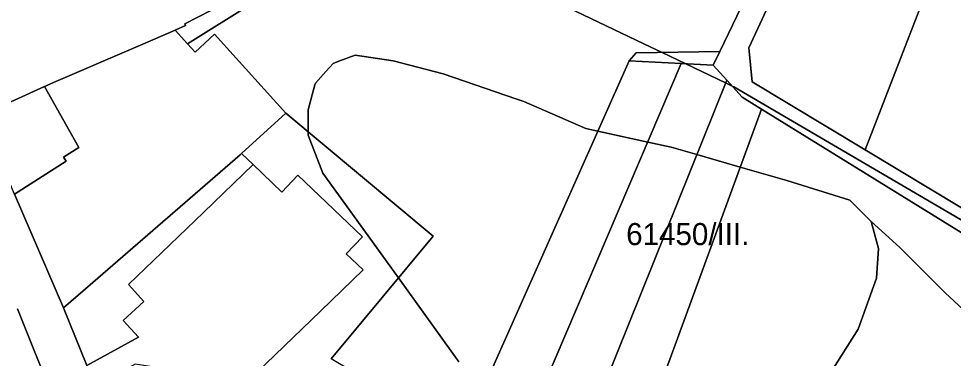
# Model space of a CAD drawing. Extents: x -522079 to -518833, y -1142400 to -1139961.
# Drawn here: x -520338.9 to -520127.5, y -1141019.5 to -1140942.7 of the extents above; entities that cross this region are included whole.
import ezdxf

# ---------------------------------------------------------------- set-up
doc = ezdxf.new("R2010")
doc.units = 0
for name, color, linetype in [('95560013', 7, 'Continuous'), ('95590013', 7, 'Continuous'), ('95610013', 7, 'Continuous'), ('95640013', 7, 'Continuous'), ('95660013', 7, 'Continuous')]:
    doc.layers.add(name, color=color, linetype=linetype)

msp = doc.modelspace()

# ---------------------------------------------------------------- linework, layer by layer
at = {"layer": '95560013'}
msp.add_lwpolyline([(-520205.51, -1141057.7), (-520170.88, -1140963.13), (-520079.53, -1141019.58), (-520129.38, -1141144.09), (-520158.56, -1141206.98), (-520178.85, -1141202.22), (-520209, -1141207.86), (-520194.38, -1141159.65), (-520235.62, -1141148.58), (-520200.4, -1141059.73)], close=True, dxfattribs=at)
at = {"layer": '95590013'}
for points in [[(-520278.46, -1140964.1), (-520294.61, -1140946.2), (-520299.04, -1140950.24), (-520300.74, -1140948.36), (-520257.36, -1140921.21), (-520246.32, -1140932.55), (-520237.12, -1140923.52), (-520250.18, -1140910.34), (-520199.46, -1140857.65), (-520181.95, -1140869.32), (-520182.55, -1140869.96), (-520164.55, -1140881.96), (-520151.68, -1140896.26), (-520156.19, -1140899.86), (-520180.26, -1140950.09), (-520199.25, -1140950.43), (-520200.79, -1140952.24), (-520238.67, -1141037.33), (-520268.23, -1141019.69), (-520245.17, -1140991.88)], [(-520235.95, -1141044.56), (-520241.17, -1141042.05), (-520238.67, -1141037.33), (-520200.79, -1140952.24), (-520189.01, -1140952.86), (-520229.4, -1141047.39), (-520230.46, -1141046.93)], [(-520181.77, -1140953.24), (-520178.74, -1140956.58), (-520217.35, -1141052.59), (-520219.97, -1141051.46), (-520227.89, -1141048.04), (-520229.4, -1141047.39), (-520189.01, -1140952.86)], [(-520217.35, -1141052.59), (-520178.74, -1140956.58), (-520175.23, -1140960.44), (-520170.88, -1140963.13), (-520205.51, -1141057.7)]]:
    msp.add_lwpolyline(points, close=True, dxfattribs=at)
msp.add_lwpolyline([(-520295.32, -1141032.65), (-520270.67, -1141008.89), (-520260.98, -1140999.54), (-520264.81, -1140995.88), (-520261.15, -1140992.05), (-520275.75, -1140978.09), (-520279.41, -1140981.92), (-520285.91, -1140975.7), (-520288.51, -1140973.21), (-520278.46, -1140964.1), (-520245.17, -1140991.88), (-520268.23, -1141019.69)], dxfattribs=at)
at = {"layer": '95610013'}
for points in [[(-520154.18, -1140907.23), (-520136.24, -1140924.81), (-520129.31, -1140925.55), (-520147.43, -1140972.36), (-520172.97, -1140956.99), (-520173.77, -1140949.3)], [(-520129.31, -1140925.55), (-520124.49, -1140925.8), (-520100.12, -1140914.78), (-520097.88, -1140916.76), (-520125.63, -1140985.48), (-520147.43, -1140972.36)]]:
    msp.add_lwpolyline(points, close=True, dxfattribs=at)
at = {"layer": '95640013'}
for points in [[(-520079.53, -1141019.58), (-520170.88, -1140963.13), (-520175.23, -1140960.44), (-520178.74, -1140956.58), (-520181.77, -1140953.24), (-520180.26, -1140950.09), (-520156.19, -1140899.86), (-520151.68, -1140896.26), (-520149.94, -1140892.73), (-520146.75, -1140896.12), (-520154.18, -1140907.23), (-520173.77, -1140949.3), (-520172.97, -1140956.99), (-520147.43, -1140972.36), (-520125.63, -1140985.48), (-520084.54, -1141010.19), (-520030.55, -1141043.1), (-520027.48, -1141044.21), (-519988.12, -1141058.45), (-519949.16, -1141072.54), (-519944.08, -1141074.41), (-519948.1, -1141084.44), (-519951.21, -1141077.01), (-520032.33, -1141047.7)], [(-520301.23, -1140944.23), (-520301.37, -1140943.86), (-520295.5, -1140940.8), (-520294.04, -1140940.04), (-520260.36, -1140918.14), (-520255, -1140914.65), (-520250.52, -1140910), (-520250.18, -1140910.34), (-520237.12, -1140923.52), (-520246.32, -1140932.55), (-520257.36, -1140921.21), (-520300.74, -1140948.36), (-520303.52, -1140945.28)], [(-520301.23, -1140944.23), (-520303.52, -1140945.28), (-520311.37, -1140948.65), (-520312.42, -1140949.1), (-520330.57, -1140956.9), (-520333.07, -1140958.03), (-520347.56, -1140964.58), (-520357.85, -1140939.9), (-520356.86, -1140939.57), (-520333.64, -1140931.91), (-520328.35, -1140930.16), (-520327.1, -1140929.75), (-520320.68, -1140927.43), (-520309.29, -1140923.33), (-520304.25, -1140936.55), (-520303.17, -1140939.4), (-520297.35, -1140935.94), (-520295.5, -1140940.8), (-520301.37, -1140943.86)], [(-520333.07, -1140958.03), (-520330.57, -1140956.9), (-520312.42, -1140949.1), (-520311.37, -1140948.65), (-520303.52, -1140945.28), (-520300.74, -1140948.36), (-520299.04, -1140950.24), (-520294.61, -1140946.2), (-520278.46, -1140964.1), (-520288.51, -1140973.21), (-520288.83, -1140973.5), (-520322.15, -1141002.36), (-520328.8, -1141008.12), (-520339.88, -1140982.4), (-520336.31, -1140980.12), (-520328.21, -1140974.96), (-520328.8, -1140974.04), (-520325.3, -1140971.81)], [(-520181.77, -1140953.24), (-520189.01, -1140952.86), (-520200.79, -1140952.24), (-520199.25, -1140950.43), (-520180.26, -1140950.09)], [(-520333.07, -1140958.03), (-520325.3, -1140971.81), (-520328.8, -1140974.04), (-520328.21, -1140974.96), (-520336.31, -1140980.12), (-520339.88, -1140982.4), (-520347.56, -1140964.58)], [(-520310.61, -1141006.67), (-520315.31, -1141011.02), (-520311.83, -1141014.78), (-520323.52, -1141021.14), (-520328.8, -1141008.12), (-520322.15, -1141002.36), (-520288.83, -1140973.5), (-520288.51, -1140973.21), (-520285.91, -1140975.7), (-520297.15, -1140986.51), (-520314.09, -1141002.81)], [(-520261.15, -1140992.05), (-520264.81, -1140995.88), (-520260.98, -1140999.54), (-520270.67, -1141008.89), (-520295.32, -1141032.65), (-520299.78, -1141027.82), (-520301.02, -1141029.07), (-520307.7, -1141021.63), (-520312.58, -1141020.86), (-520321.6, -1141025.87), (-520323.52, -1141021.14), (-520311.83, -1141014.78), (-520315.31, -1141011.02), (-520310.61, -1141006.67), (-520314.09, -1141002.81), (-520297.15, -1140986.51), (-520285.91, -1140975.7), (-520279.41, -1140981.92), (-520275.75, -1140978.09)]]:
    msp.add_lwpolyline(points, close=True, dxfattribs=at)
for points in [[(-520339.88, -1140982.4), (-520328.8, -1141008.12), (-520323.52, -1141021.14)], [(-520339.2, -1141008.34), (-520330.66, -1141029.65), (-520324.76, -1141047.17), (-520321.07, -1141060.89), (-520319.27, -1141070.53), (-520318.44, -1141077.73), (-520317.76, -1141090.48), (-520318.04, -1141094.37), (-520318.78, -1141100.08), (-520325.12, -1141113.35), (-520332.74, -1141125.19), (-520337.15, -1141133.73), (-520339.09, -1141141.84)], [(-520339.09, -1141141.84), (-520337.15, -1141133.73), (-520332.74, -1141125.19), (-520325.12, -1141113.35), (-520318.78, -1141100.08), (-520318.04, -1141094.37), (-520317.76, -1141090.48), (-520318.44, -1141077.73), (-520319.27, -1141070.53), (-520321.07, -1141060.89), (-520324.76, -1141047.17), (-520330.66, -1141029.65), (-520339.2, -1141008.34)]]:
    msp.add_lwpolyline(points, dxfattribs=at)
at = {"layer": '95660013'}
for points in [[(-520000, -1141056.45), (-520011.71, -1141051.75), (-520029.88, -1141044.45), (-520090.04, -1141009.08), (-520177.16, -1140958.1), (-520177.51, -1140957.94), (-520179, -1140957.22), (-520187.97, -1140952.91), (-520193.37, -1140950.32), (-520197.48, -1140948.35), (-520236.79, -1140929.49), (-520241.05, -1140927.38), (-520260.08, -1140917.96), (-520260.95, -1140917.52), (-520263.93, -1140916.05), (-520267.12, -1140914.47), (-520274.28, -1140910.93), (-520277.76, -1140909.2), (-520287.26, -1140905.6), (-520291.47, -1140904.01), (-520313.41, -1140895.68), (-520320.28, -1140893.08), (-520338.07, -1140887.2), (-520355.25, -1140881.53)], [(-520355.25, -1140881.53), (-520338.07, -1140887.2), (-520320.28, -1140893.08), (-520313.41, -1140895.68), (-520291.47, -1140904.01), (-520287.26, -1140905.6), (-520277.76, -1140909.2), (-520274.28, -1140910.93), (-520267.12, -1140914.47), (-520263.93, -1140916.05), (-520260.95, -1140917.52), (-520260.08, -1140917.96), (-520241.05, -1140927.38), (-520236.79, -1140929.49), (-520197.48, -1140948.35), (-520193.37, -1140950.32), (-520187.97, -1140952.91), (-520179, -1140957.22), (-520177.51, -1140957.94), (-520177.16, -1140958.1), (-520090.04, -1141009.08), (-520029.88, -1141044.45), (-520011.71, -1141051.75), (-520000, -1141056.45)], [(-520097.47, -1141034.19), (-520129.32, -1141004.76), (-520132.12, -1141001.95), (-520139.58, -1140994.46), (-520146.08, -1140988.57), (-520150.9, -1140983.74), (-520165.15, -1140979.32), (-520175.69, -1140976.27), (-520185.52, -1140973.44), (-520191.34, -1140971.76), (-520196.59, -1140970.61), (-520207.87, -1140968.15), (-520210.62, -1140967.55), (-520224.66, -1140961.45), (-520226.23, -1140960.91), (-520242.89, -1140955.15), (-520254.2, -1140952.21), (-520262.79, -1140950.95), (-520266.47, -1140952.33), (-520267.82, -1140952.84), (-520269.45, -1140954.64), (-520271.81, -1140957.25), (-520271.92, -1140957.68), (-520273.48, -1140963.35), (-520273.48, -1140968.25), (-520273.48, -1140969.02), (-520270.13, -1140977.64), (-520256.93, -1140995.93), (-520253.02, -1141001.35), (-520239.33, -1141020.32)], [(-520239.33, -1141020.32), (-520253.02, -1141001.35), (-520256.93, -1140995.93), (-520270.13, -1140977.64), (-520273.48, -1140969.02), (-520273.48, -1140968.25), (-520273.48, -1140963.35), (-520271.92, -1140957.68), (-520271.81, -1140957.25), (-520269.45, -1140954.64), (-520267.82, -1140952.84), (-520266.47, -1140952.33), (-520262.79, -1140950.95), (-520254.2, -1140952.21), (-520242.89, -1140955.15), (-520226.23, -1140960.91), (-520224.66, -1140961.45), (-520210.62, -1140967.55), (-520207.87, -1140968.15), (-520196.59, -1140970.61), (-520191.34, -1140971.76), (-520185.52, -1140973.44), (-520175.69, -1140976.27), (-520165.15, -1140979.32), (-520150.9, -1140983.74), (-520146.08, -1140988.57), (-520144.4, -1140994.67), (-520144.82, -1141001.4), (-520149.01, -1141012.96), (-520155.09, -1141022.62)], [(-520155.09, -1141022.62), (-520149.01, -1141012.96), (-520144.82, -1141001.4), (-520144.4, -1140994.67), (-520146.08, -1140988.57), (-520139.58, -1140994.46), (-520132.12, -1141001.95), (-520129.32, -1141004.76), (-520097.47, -1141034.19)]]:
    msp.add_lwpolyline(points, dxfattribs=at)

# ---------------------------------------------------------------- texts
msp.add_text('61450/III.', height=5, rotation=360, dxfattribs=at).set_placement((-520201.49, -1140993.93))

doc.saveas('drawing.dxf')
